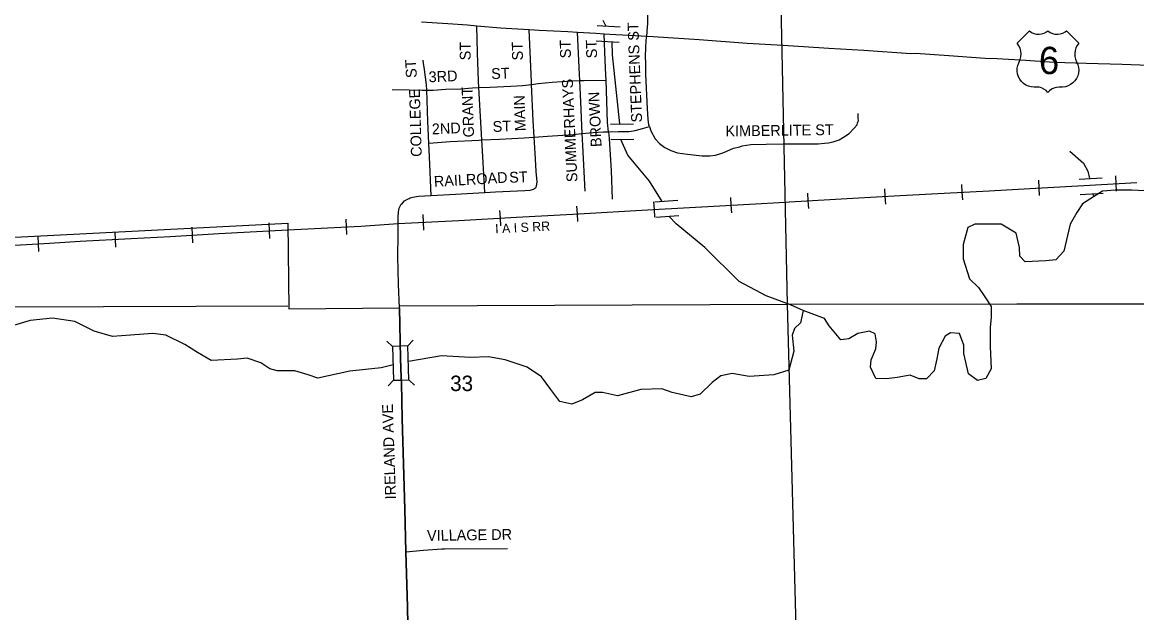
# Model space of a CAD drawing. Extents: x 281.94 to 289.14, y 116.09 to 120.89.
# Drawn here: x 283.686 to 285.132, y 118.031 to 118.797 of the extents above; entities that cross this region are included whole.
import ezdxf

# ---------------------------------------------------------------- set-up
doc = ezdxf.new("R2010")
doc.units = 0
for name, color, linetype in [('tdCiCityStreetCL', 7, 'Continuous'), ('tdCiCityStreetTxt', 7, 'Continuous'), ('tdCiCorpBndry', 7, 'Continuous'), ('tdCiCorpBndryPart', 7, 'Continuous'), ('tdCiHydroRiver', 7, 'Continuous'), ('tdCiPriCL', 7, 'Continuous'), ('tdCiPriDiv', 7, 'Continuous'), ('tdCiRRCL', 7, 'Continuous'), ('tdCiRROwnerTxt', 7, 'Continuous'), ('tdCiSecCL', 7, 'Continuous'), ('tdCiSecText', 7, 'Continuous'), ('tdCiSectLine', 7, 'Continuous'), ('tdCiSectNmbr', 7, 'Continuous'), ('tdCiShieldPriUsRte', 7, 'Continuous'), ('tdCiStrucCartoClvrt', 7, 'Continuous'), ('tdCiStrucDataMuni', 7, 'Continuous')]:
    doc.layers.add(name, color=color, linetype=linetype)

msp = doc.modelspace()

# ---------------------------------------------------------------- linework, layer by layer
at = {"layer": 'tdCiCityStreetCL'}
for points in [[(284.4999, 118.6614), (284.4991, 118.6639), (284.4984, 118.6709), (284.4974, 118.6845), (284.4951, 118.7296), (284.4951, 118.7436), (284.4946, 118.753), (284.4958, 118.7737), (284.4963, 118.779), (284.4973, 118.7903), (284.4976, 118.7952), (284.498, 118.8033), (284.4973, 118.8263), (284.4965, 118.8381)], [(284.2785, 118.712), (284.2781, 118.7205), (284.277, 118.7572), (284.2761, 118.7924)], [(284.347, 118.7163), (284.3469, 118.7197), (284.3437, 118.7875)], [(284.4096, 118.7212), (284.4093, 118.7291), (284.4068, 118.7841)], [(284.4438, 118.7218), (284.4435, 118.7281), (284.4421, 118.7582), (284.4416, 118.7703), (284.4413, 118.782)], [(284.2112, 118.7088), (284.2109, 118.7155), (284.2081, 118.7357), (284.2069, 118.7439), (284.2062, 118.7478)], [(284.2785, 118.712), (284.2935, 118.7128), (284.32, 118.7141), (284.3354, 118.7148), (284.347, 118.7163)], [(284.347, 118.7163), (284.3556, 118.7175), (284.3736, 118.7192), (284.399, 118.7207), (284.4096, 118.7212)], [(284.3503, 118.6477), (284.349, 118.6692), (284.347, 118.7163)], [(284.4096, 118.7212), (284.4153, 118.7214), (284.4438, 118.7218)], [(284.4126, 118.6525), (284.4108, 118.6936), (284.4096, 118.7212)], [(284.4468, 118.6547), (284.4456, 118.6667), (284.4438, 118.7218)], [(284.1663, 118.7094), (284.1882, 118.7091), (284.2052, 118.7089), (284.2112, 118.7088)], [(284.2112, 118.7088), (284.2195, 118.7086), (284.236, 118.7099), (284.2551, 118.7106), (284.2703, 118.7116), (284.2785, 118.712)], [(284.2138, 118.6401), (284.2126, 118.6682), (284.2118, 118.6958), (284.2112, 118.7088)], [(284.2823, 118.6441), (284.2785, 118.712)], [(284.4999, 118.6614), (284.5016, 118.6559), (284.5075, 118.6457), (284.5129, 118.6396), (284.5198, 118.6344), (284.5275, 118.6305), (284.5364, 118.6275), (284.5492, 118.6255), (284.5684, 118.6235), (284.5783, 118.6235), (284.5854, 118.6245), (284.5923, 118.6265), (284.5965, 118.628), (284.6089, 118.6334), (284.6172, 118.6352), (284.6202, 118.6366), (284.6313, 118.6383), (284.6513, 118.6386), (284.6735, 118.6391), (284.7189, 118.6393), (284.7269, 118.6399), (284.732, 118.6406), (284.7384, 118.6418), (284.746, 118.6444), (284.7514, 118.6476), (284.7588, 118.6527), (284.7655, 118.6594), (284.7693, 118.6638), (284.7696, 118.6664), (284.7709, 118.6689), (284.7706, 118.6725), (284.7706, 118.6785)], [(284.4468, 118.6547), (284.4597, 118.6549), (284.463, 118.6549), (284.469, 118.655), (284.4735, 118.6551), (284.4814, 118.6563), (284.4908, 118.6588), (284.494, 118.6597), (284.4999, 118.6614)], [(284.2138, 118.6401), (284.2414, 118.642), (284.2789, 118.644), (284.2823, 118.6441)], [(284.2823, 118.6441), (284.3053, 118.645), (284.3374, 118.6467), (284.3503, 118.6477)], [(284.2863, 118.5759), (284.2844, 118.6149), (284.2823, 118.6441)], [(284.2863, 118.5759), (284.3001, 118.5767), (284.3381, 118.5787), (284.3453, 118.5789), (284.3483, 118.5799), (284.3499, 118.5804), (284.3514, 118.5816), (284.3524, 118.5824), (284.3534, 118.5843), (284.3541, 118.5898), (284.3531, 118.6033), (284.3517, 118.627), (284.3503, 118.6477)], [(284.3503, 118.6477), (284.3677, 118.6489), (284.401, 118.6514), (284.4126, 118.6525)], [(284.4126, 118.6525), (284.4269, 118.6539), (284.4402, 118.6546), (284.4468, 118.6547)], [(284.4167, 118.5779), (284.4133, 118.6369), (284.4126, 118.6525)], [(284.4468, 118.6547), (284.4476, 118.646), (284.4499, 118.6112), (284.4503, 118.6043), (284.4514, 118.5674)], [(284.2168, 118.5721), (284.2146, 118.6223), (284.2138, 118.6401)], [(284.1757, 118.4265), (284.1744, 118.4568), (284.1736, 118.4931), (284.1739, 118.5206), (284.174, 118.5356), (284.1741, 118.5439), (284.1744, 118.5506), (284.1751, 118.5557), (284.1778, 118.5607), (284.1796, 118.5621), (284.182, 118.5651), (284.1859, 118.5675), (284.1881, 118.5684), (284.1895, 118.569), (284.1928, 118.5699), (284.2002, 118.571), (284.2168, 118.5721)], [(284.2168, 118.5721), (284.2483, 118.5737), (284.2708, 118.575), (284.2863, 118.5759)], [(284.1841, 118.1097), (284.2067, 118.1118), (284.2307, 118.1135), (284.2339, 118.1135), (284.3158, 118.1139)]]:
    msp.add_lwpolyline(points, dxfattribs=at)
at = {"layer": 'tdCiCorpBndry'}
msp.add_lwpolyline([(283.019, 118.4842), (284.0309, 118.536), (284.0322, 118.4252), (284.1757, 118.4265), (284.1771, 118.3606), (284.1775, 118.3482), (284.1778, 118.3364), (284.1781, 118.3291), (284.1793, 118.2822), (284.1827, 118.1651), (284.1841, 118.1097), (284.1861, 118.0386), (284.1867, 118.0153)], dxfattribs=at)
at = {"layer": 'tdCiCorpBndryPart'}
msp.add_lwpolyline([(283.0197, 118.9514), (283.019, 118.4842), (284.0309, 118.536), (284.0322, 118.4252), (284.1757, 118.4265)], dxfattribs=at)
at = {"layer": 'tdCiHydroRiver'}
for points in [[(284.4395, 118.7994), (284.4435, 118.7919)], [(284.4614, 118.6649), (284.452, 118.7547), (284.4515, 118.7714)], [(284.5164, 118.5642), (284.4998, 118.5907), (284.4719, 118.6245), (284.4628, 118.6449)], [(285.0452, 118.6295), (285.0627, 118.6141), (285.0685, 118.6035), (285.0706, 118.5941)], [(285.1689, 118.559), (285.1622, 118.5691), (285.142, 118.5781), (285.1256, 118.5792), (285.1039, 118.5792), (285.0875, 118.5776), (285.0759, 118.5702), (285.0616, 118.5612), (285.0542, 118.5501), (285.0457, 118.5347)], [(285.075, 118.5744), (285.0759, 118.5702)], [(285.0457, 118.5347), (285.0374, 118.4997), (285.0271, 118.4887), (285.014, 118.4873), (284.9872, 118.4859), (284.9804, 118.4935), (284.9797, 118.5045), (284.9797, 118.5045), (284.9755, 118.523), (284.9563, 118.5347), (284.922, 118.5347), (284.913, 118.5306), (284.9068, 118.5086), (284.9068, 118.49), (284.9151, 118.4639), (284.9268, 118.4529), (284.935, 118.4406), (284.9433, 118.4282), (284.9433, 118.4138), (284.9419, 118.4014), (284.9419, 118.376), (284.9433, 118.3471), (284.9364, 118.3348), (284.9254, 118.332), (284.9137, 118.3409), (284.9075, 118.3671), (284.9075, 118.3781), (284.902, 118.3932), (284.902, 118.3932), (284.8903, 118.3939), (284.8835, 118.3897), (284.8752, 118.3739), (284.8725, 118.3602), (284.869, 118.3444), (284.8594, 118.3341), (284.8498, 118.3341), (284.8381, 118.3389), (284.821, 118.3361), (284.8072, 118.3341), (284.7935, 118.3348), (284.7866, 118.3492), (284.7873, 118.3588), (284.7935, 118.3732), (284.7942, 118.3822), (284.7928, 118.3925), (284.7852, 118.3959), (284.7701, 118.3932), (284.7584, 118.3863), (284.7481, 118.3849), (284.733, 118.4028), (284.7268, 118.4124), (284.6993, 118.4227), (284.6829, 118.4303), (284.6513, 118.4419), (284.6162, 118.4605), (284.5716, 118.5045), (284.5345, 118.5354), (284.5254, 118.5448)], [(284.1674, 118.3522), (284.1519, 118.3485), (284.1112, 118.3441), (284.0698, 118.3352), (284.0572, 118.3396), (284.0401, 118.3448), (284.0172, 118.3448), (284.0076, 118.347), (283.9957, 118.3552), (283.978, 118.3611), (283.9654, 118.3596), (283.9313, 118.3582), (283.9313, 118.3582), (283.9136, 118.3685), (283.8973, 118.3789), (283.8728, 118.3907), (283.8558, 118.3929), (283.8269, 118.3907), (283.8033, 118.3892), (283.7796, 118.3959), (283.7544, 118.4085), (283.7255, 118.4129), (283.6967, 118.41), (283.6752, 118.4033)], [(284.6993, 118.4227), (284.696, 118.407), (284.6879, 118.3996), (284.6849, 118.3907), (284.6871, 118.37), (284.6805, 118.3456), (284.6612, 118.3396), (284.6294, 118.3374), (284.6072, 118.3411), (284.5924, 118.3382), (284.5813, 118.3293), (284.5657, 118.3145), (284.5539, 118.3108), (284.5295, 118.3167), (284.5161, 118.3211), (284.4887, 118.3204), (284.4584, 118.3123), (284.4391, 118.3167), (284.4295, 118.3167), (284.4132, 118.3071), (284.3992, 118.3012), (284.3836, 118.3049), (284.3718, 118.3204), (284.3599, 118.3367), (284.3414, 118.3493), (284.3126, 118.3589), (284.2911, 118.3626), (284.2674, 118.3619), (284.2304, 118.3641), (284.1873, 118.3569)]]:
    msp.add_lwpolyline(points, dxfattribs=at)
at = {"layer": 'tdCiPriCL'}
msp.add_lwpolyline([(284.2042, 118.7975), (284.2383, 118.7952), (284.264, 118.7935), (284.2761, 118.7924), (284.3065, 118.7898), (284.3437, 118.7875), (284.3567, 118.7867), (284.3939, 118.7849), (284.4068, 118.7841), (284.4304, 118.7826), (284.4413, 118.782), (284.4563, 118.7811), (284.4655, 118.7806), (284.489, 118.7793), (284.4963, 118.779), (284.5047, 118.7785), (284.5642, 118.7746), (284.6267, 118.7699), (284.6733, 118.7673), (284.7327, 118.7634), (284.7778, 118.7607), (284.839, 118.7561), (284.8448, 118.7566), (284.8883, 118.7535), (284.9353, 118.7504), (284.9507, 118.7498), (284.9883, 118.7475), (285.0249, 118.7452), (285.0663, 118.7439), (285.1132, 118.7425), (285.1599, 118.7407)], dxfattribs=at)
at = {"layer": 'tdCiPriDiv'}
msp.add_lwpolyline([(284.2042, 118.7975), (284.2383, 118.7952), (284.264, 118.7935), (284.2761, 118.7924), (284.3065, 118.7898), (284.3437, 118.7875), (284.3567, 118.7867), (284.3939, 118.7849), (284.4068, 118.7841), (284.4304, 118.7826), (284.4413, 118.782), (284.4563, 118.7811), (284.4655, 118.7806), (284.489, 118.7793), (284.4963, 118.779), (284.5047, 118.7785), (284.5642, 118.7746), (284.6267, 118.7699), (284.6733, 118.7673), (284.7327, 118.7634), (284.7778, 118.7607), (284.839, 118.7561), (284.8448, 118.7566), (284.8883, 118.7535), (284.9353, 118.7504), (284.9507, 118.7498), (284.9883, 118.7475), (285.0249, 118.7452), (285.0663, 118.7439), (285.1132, 118.7425), (285.1599, 118.7407)], dxfattribs=at)
at = {"layer": 'tdCiRRCL'}
for points in [[(283.6768, 118.5076), (283.7219, 118.5104), (283.7615, 118.5127), (283.8278, 118.5161), (283.8782, 118.5191), (283.9414, 118.5228), (284.031, 118.5277), (284.1256, 118.5324), (284.174, 118.5356), (284.2527, 118.5396), (284.3274, 118.5439), (284.4005, 118.548), (284.5047, 118.5537), (284.5836, 118.5584), (284.6761, 118.5635), (284.6815, 118.5638), (284.7635, 118.5686), (284.8253, 118.5719), (284.8823, 118.575), (284.9406, 118.5783), (284.9932, 118.5813), (285.0632, 118.5852), (285.132, 118.5889)], [(283.6768, 118.5076), (283.7219, 118.5104), (283.7615, 118.5127), (283.8278, 118.5161), (283.8782, 118.5191), (283.9414, 118.5228), (284.031, 118.5277), (284.1256, 118.5324), (284.174, 118.5356), (284.2527, 118.5396), (284.3274, 118.5439), (284.4005, 118.548), (284.5047, 118.5537), (284.5836, 118.5584), (284.6761, 118.5635), (284.6815, 118.5638), (284.7635, 118.5686), (284.8253, 118.5719), (284.8823, 118.575), (284.9406, 118.5783), (284.9932, 118.5813), (285.0632, 118.5852), (285.132, 118.5889)], [(284.9062, 118.5663), (284.9056, 118.5763), (284.9051, 118.5863)], [(285.006, 118.572), (285.0055, 118.5819), (285.0049, 118.5919)], [(285.1059, 118.5775), (285.1053, 118.5874), (285.1048, 118.5974)], [(284.7065, 118.5552), (284.7059, 118.5652), (284.7054, 118.5752)], [(284.8063, 118.5608), (284.8058, 118.5708), (284.8052, 118.5808)], [(284.407, 118.5384), (284.4064, 118.5483), (284.4059, 118.5583)], [(284.5069, 118.5438), (284.5063, 118.5538), (284.5057, 118.5638)], [(284.6066, 118.5496), (284.6061, 118.5596), (284.6055, 118.5696)], [(284.1074, 118.5215), (284.1069, 118.5315), (284.1064, 118.5414)], [(284.2072, 118.5273), (284.2067, 118.5373), (284.2062, 118.5473)], [(284.3071, 118.5327), (284.3066, 118.5427), (284.306, 118.5527)], [(283.9078, 118.5108), (283.9072, 118.5208), (283.9066, 118.5308)], [(284.0076, 118.5164), (284.007, 118.5264), (284.0065, 118.5364)], [(283.7081, 118.4996), (283.7075, 118.5095), (283.7069, 118.5195)], [(283.8078, 118.505), (283.8073, 118.515), (283.8068, 118.525)]]:
    msp.add_lwpolyline(points, dxfattribs=at)
at = {"layer": 'tdCiSecCL'}
msp.add_lwpolyline([(284.1867, 118.0153), (284.1861, 118.0386), (284.1841, 118.1097), (284.1827, 118.1651), (284.1793, 118.2822), (284.1781, 118.3291), (284.1778, 118.3364), (284.1775, 118.3482), (284.1771, 118.3606), (284.1757, 118.4265)], dxfattribs=at)
at = {"layer": 'tdCiSectLine'}
for points in [[(284.7005, 117.6247), (284.6788, 118.4309), (284.6579, 119.4326), (284.6484, 120.235)], [(284.9764, 118.4314), (285.1807, 118.4315), (285.6871, 118.4319), (286.4184, 118.4403)], [(283.0233, 118.4242), (283.6724, 118.4278), (284.0307, 118.4288)], [(284.1759, 118.429), (284.6788, 118.4309), (284.9764, 118.4314)]]:
    msp.add_lwpolyline(points, dxfattribs=at)
at = {"layer": 'tdCiShieldPriUsRte'}
msp.add_lwpolyline([(285.0488, 118.7778), (285.0567, 118.7699), (285.0546, 118.7668), (285.0529, 118.7635), (285.0519, 118.76), (285.0515, 118.7563), (285.0517, 118.7526), (285.0525, 118.749), (285.0539, 118.7456), (285.0555, 118.7418), (285.0564, 118.7382), (285.0567, 118.7345), (285.0563, 118.7308), (285.0554, 118.7272), (285.0538, 118.7239), (285.0518, 118.7208), (285.0492, 118.7182), (285.0462, 118.716), (285.0429, 118.7143), (285.0394, 118.7132), (285.0357, 118.7127), (285.0312, 118.7127), (285.0278, 118.7124), (285.0246, 118.7115), (285.0215, 118.71), (285.0188, 118.7079), (285.0168, 118.7058), (285.0144, 118.7082), (285.0116, 118.7102), (285.0086, 118.7116), (285.0053, 118.7125), (285.0023, 118.7127), (284.9989, 118.7127), (284.9952, 118.713), (284.9916, 118.7139), (284.9883, 118.7154), (284.9852, 118.7175), (284.9825, 118.72), (284.9803, 118.723), (284.9786, 118.7262), (284.9774, 118.7298), (284.9769, 118.7334), (284.977, 118.7371), (284.9777, 118.7407), (284.979, 118.7442), (284.9809, 118.7485), (284.9818, 118.7521), (284.9821, 118.7558), (284.9817, 118.7595), (284.9808, 118.7631), (284.9792, 118.7664), (284.9768, 118.7699), (284.9927, 118.7857), (284.9955, 118.7837), (284.9985, 118.7823), (285.0018, 118.7815), (285.0052, 118.7813), (285.0086, 118.7817), (285.0118, 118.7827), (285.0148, 118.7842), (285.0168, 118.7857), (285.0196, 118.7837), (285.0226, 118.7823), (285.0259, 118.7815), (285.0294, 118.7812), (285.0327, 118.7817), (285.0359, 118.7827), (285.0389, 118.7842), (285.0409, 118.7857)], close=True, dxfattribs=at)
at = {"layer": 'tdCiStrucCartoClvrt'}
for p, q in [((284.4319, 118.7925), (284.4618, 118.7909)), ((284.4307, 118.7726), (284.4607, 118.7709)), ((284.4493, 118.6647), (284.4793, 118.6652)), ((284.4497, 118.6447), (284.4797, 118.6452)), ((285.0571, 118.5932), (285.0871, 118.5952)), ((285.0585, 118.5733), (285.0884, 118.5752)), ((284.5368, 118.5655), (284.5068, 118.5636)), ((284.538, 118.5455), (284.508, 118.5437))]:
    msp.add_line(p, q, dxfattribs=at)
at = {"layer": 'tdCiStrucDataMuni'}
for points in [[(284.1867, 118.3769), (284.1767, 118.3766), (284.1667, 118.3763), (284.1594, 118.3832)], [(284.1879, 118.3329), (284.1867, 118.3769), (284.1935, 118.3842)], [(284.1667, 118.3763), (284.168, 118.3323), (284.1611, 118.325)], [(284.168, 118.3323), (284.178, 118.3326), (284.1879, 118.3329), (284.1952, 118.326)]]:
    msp.add_lwpolyline(points, dxfattribs=at)

# ---------------------------------------------------------------- texts
at = {"layer": 'tdCiCityStreetTxt'}
for s, rotation, p in [('STEPHENS ST', 92.2072, (284.4904, 118.6671)), ('ST', 91.498, (284.3981, 118.7502)), ('ST', 91.8381, (284.4321, 118.7503)), ('ST', 90.4312, (284.268, 118.7475)), ('ST', 91.4867, (284.3359, 118.7475)), ('ST', 93.3246, (284.1983, 118.725)), ('3RD', 2.5285, (284.2138, 118.7189)), ('ST', 1.9638, (284.2948, 118.7231)), ('SUMMERHAYS', 92.6662, (284.4066, 118.5897)), ('COLLEGE', 91.7237, (284.2047, 118.6224)), ('GRANT', 91.9822, (284.2725, 118.6477)), ('MAIN', 92.1727, (284.3396, 118.6557)), ('BROWN', 92.6464, (284.4379, 118.6353)), ('2ND', 2.6137, (284.218, 118.6513)), ('ST', 2.2942, (284.2968, 118.6544)), ('KIMBERLITE ST', 0.7354, (284.5985, 118.6487)), ('RAILROAD', 3.3819, (284.2207, 118.5832)), ('ST', 2.1088, (284.3182, 118.5886)), ('VILLAGE DR', 0.841, (284.2115, 118.1239))]:
    msp.add_text(s, height=0.014, rotation=rotation, dxfattribs=at).set_placement(p)
at = {"layer": 'tdCiRROwnerTxt'}
msp.add_text('I A I S RR', height=0.012, rotation=3.1115, dxfattribs=at).set_placement((284.3001, 118.5228))
at = {"layer": 'tdCiSecText'}
msp.add_text('IRELAND AVE', height=0.014, rotation=91.9246, dxfattribs=at).set_placement((284.1712, 118.1781))
at = {"layer": 'tdCiSectNmbr'}
msp.add_text('33', height=0.02, rotation=359.8775, dxfattribs=at).set_placement((284.2414, 118.3184))
at = {"layer": 'tdCiShieldPriUsRte'}
msp.add_text('6', height=0.0354, dxfattribs=at).set_placement((285.005, 118.7296))

doc.saveas('drawing.dxf')
